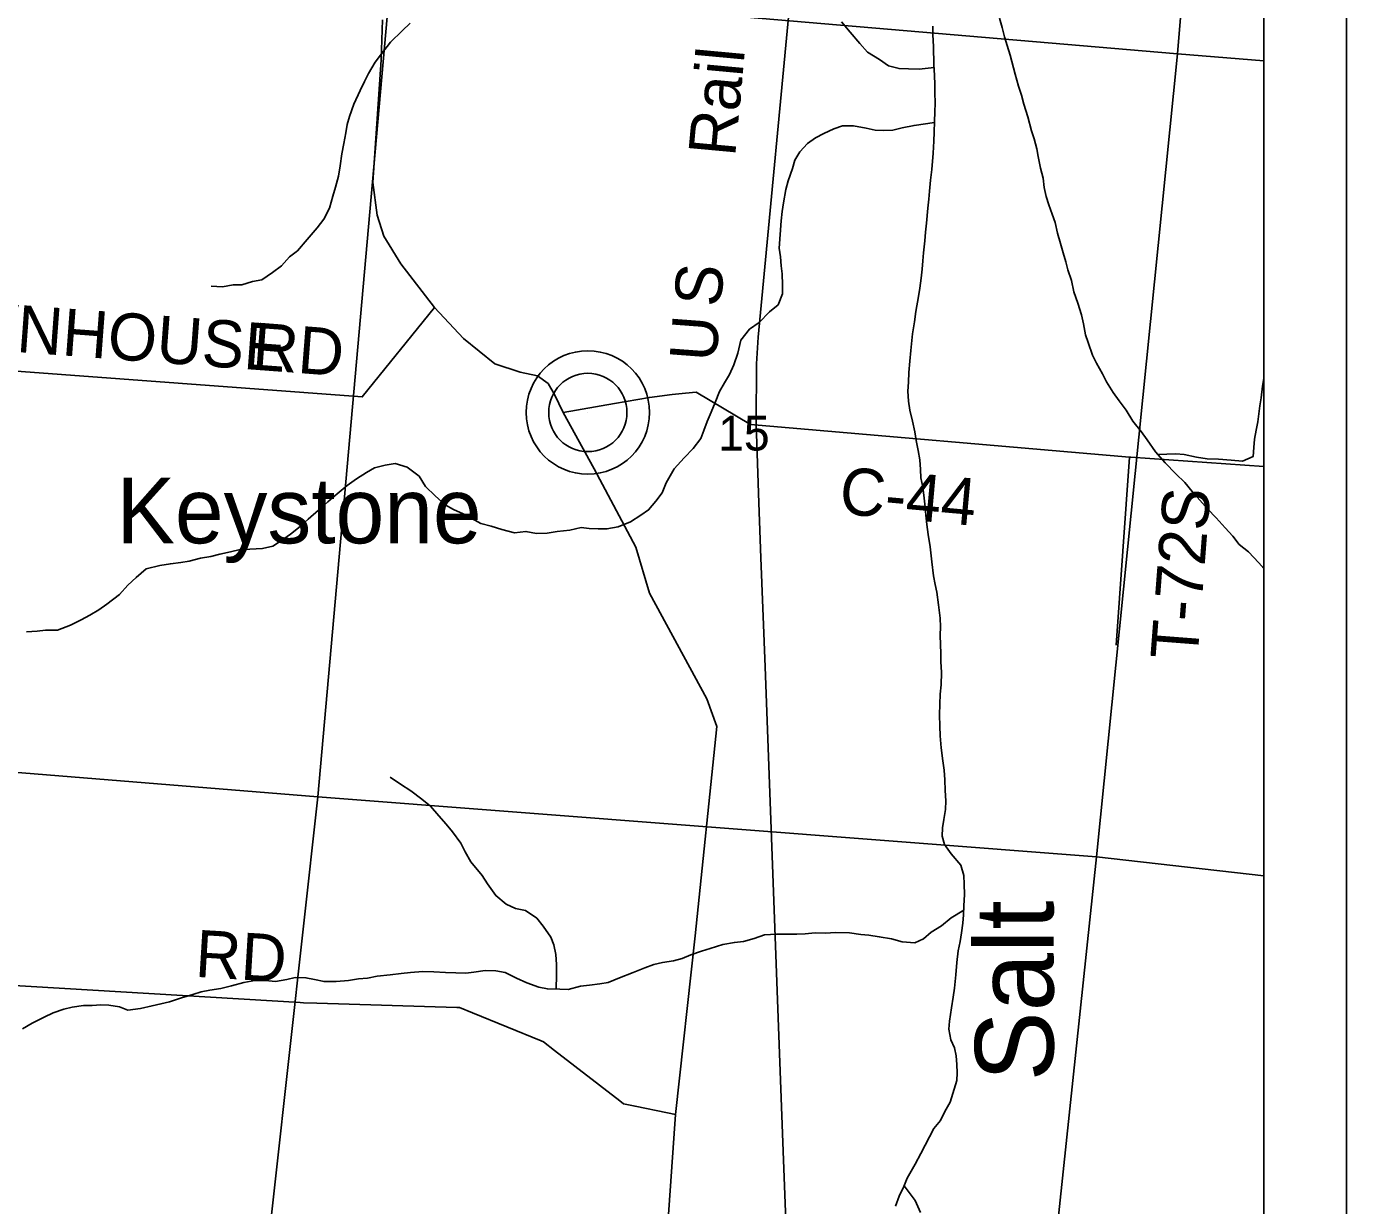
# Model space of a CAD drawing. Extents: x 0 to 34, y 0 to 22.
# Drawn here: x 28.825 to 30.417, y 16.193 to 17.615 of the extents above; entities that cross this region are included whole.
import ezdxf

# ---------------------------------------------------------------- set-up
doc = ezdxf.new("R2010")
doc.units = 0
for name, color, linetype in [('GM_X_Corporation', 7, 'Continuous'), ('GM_X_County_Road', 7, 'Continuous'), ('GM_X_County_Road_Text', 7, 'Continuous'), ('GM_X_Major_River', 7, 'Continuous'), ('GM_X_Major_River_Text', 7, 'Continuous'), ('GM_X_Minor_River', 7, 'Continuous'), ('GM_X_Rail_Line', 7, 'Continuous'), ('GM_X_Rail_Line_Text', 7, 'Continuous'), ('GM_X_Section_Text', 7, 'Continuous'), ('GM_X_Township_Road', 7, 'Continuous'), ('GM_X_Township_Road_Text', 7, 'Continuous'), ('GM_X_Unincorporated', 7, 'Continuous'), ('GM_X_Unincorporated_Location', 7, 'Continuous'), ('GM_X_Unincorporated_Text', 7, 'Continuous'), ('SH_Data', 7, 'Continuous')]:
    doc.layers.add(name, color=color, linetype=linetype)

msp = doc.modelspace()

# ---------------------------------------------------------------- linework, layer by layer
at = {"layer": 'GM_X_Corporation'}
msp.add_lwpolyline([(25.8273, 14.1), (30.3167, 14.1), (30.3167, 19.5906)], dxfattribs=at)
for points in [[(30.2969, 18.5954), (30.2127, 17.5822), (29.263, 17.6631), (29.2972, 18.6715)], [(30.3167, 17.5734), (30.3167, 18.5939), (30.2969, 18.5954), (30.2127, 17.5822)], [(28.2741, 17.7417), (29.263, 17.6631), (29.176, 16.6858), (28.199, 16.7653)], [(30.2127, 17.5822), (30.115, 16.6136), (29.176, 16.6858), (29.263, 17.6631)], [(30.3167, 16.5908), (30.3167, 17.5734), (30.2127, 17.5822), (30.115, 16.6136)], [(29.176, 16.6858), (29.0551, 15.5941), (28.1104, 15.671), (28.199, 16.7653)], [(30.115, 16.6136), (29.9973, 15.5007), (29.0551, 15.5941), (29.176, 16.6858)], [(30.3167, 15.4729), (30.3167, 16.5908), (30.115, 16.6136), (29.9973, 15.5007)]]:
    msp.add_lwpolyline(points, close=True, dxfattribs=at)
at = {"layer": 'GM_X_County_Road'}
for points in [[(29.5944, 16.119), (29.6075, 16.3028), (29.631, 16.5184), (29.6571, 16.7707), (29.6453, 16.804), (29.5759, 16.9315), (29.5594, 16.9871), (29.5094, 17.0817), (29.4719, 17.1493), (29.4613, 17.171), (29.4537, 17.1846), (29.4408, 17.1936), (29.42, 17.1981), (29.3897, 17.2082), (29.3517, 17.2387), (29.3169, 17.276), (29.2761, 17.3286), (29.2555, 17.3622), (29.2478, 17.3876), (29.2423, 17.427), (29.2523, 17.5746), (29.254, 17.6231)], [(29.4719, 17.1493), (29.534, 17.1603), (29.576, 17.1677), (29.6032, 17.1713), (29.6195, 17.1729), (29.6323, 17.1741), (29.6979, 17.1349), (30.1548, 17.0956), (30.1566, 17.0954), (30.3167, 17.0842)]]:
    msp.add_lwpolyline(points, dxfattribs=at)
at = {"layer": 'GM_X_Major_River'}
for points in [[(29.9176, 17.6152), (29.9179, 17.6054), (29.9186, 17.5906), (29.9191, 17.5693), (29.9198, 17.5557), (29.92, 17.5451), (29.9203, 17.5352), (29.9206, 17.5227), (29.9201, 17.5121), (29.9197, 17.5003), (29.9195, 17.4874), (29.9191, 17.4768), (29.9182, 17.4621), (29.9165, 17.4424), (29.9149, 17.4295), (29.9136, 17.4162), (29.9128, 17.4068), (29.9116, 17.3958), (29.9099, 17.3776), (29.9087, 17.367), (29.9082, 17.3564), (29.9065, 17.342), (29.9057, 17.3325), (29.9049, 17.3223), (29.9036, 17.3113), (29.902, 17.2996), (29.9004, 17.2893), (29.8972, 17.2712), (29.8956, 17.2587), (29.8932, 17.2443), (29.8911, 17.2242), (29.8899, 17.2113), (29.8886, 17.1977), (29.8882, 17.1859), (29.8877, 17.1753), (29.8883, 17.1632), (29.8901, 17.1522), (29.893, 17.1389), (29.896, 17.126), (29.8978, 17.1157), (29.8999, 17.1036), (29.9021, 17.0922), (29.9027, 17.0808), (29.9034, 17.0705), (29.9056, 17.0595), (29.9073, 17.0462), (29.9084, 17.0352), (29.9091, 17.0258), (29.9105, 17.0144), (29.9122, 17.0022), (29.9144, 16.9874), (29.9165, 16.9692), (29.9186, 16.9525), (29.9204, 16.9422), (29.9226, 16.9327), (29.9247, 16.9176), (29.9265, 16.9016), (29.9268, 16.891), (29.9267, 16.8811), (29.927, 16.8694), (29.9272, 16.8592), (29.9275, 16.8493), (29.9282, 16.836), (29.9277, 16.8212), (29.9264, 16.8099), (29.9263, 16.7977), (29.9258, 16.7849), (29.9261, 16.7712), (29.9264, 16.7594), (29.9277, 16.745), (29.9299, 16.7295), (29.9313, 16.7181), (29.9323, 16.7063)], [(29.9323, 16.7063), (29.9326, 16.6938), (29.9332, 16.6813), (29.9331, 16.6707), (29.9311, 16.6586), (29.9292, 16.6487), (29.9291, 16.6385), (29.9316, 16.6286), (29.9399, 16.6171), (29.9514, 16.6034), (29.9551, 16.5912), (29.9554, 16.5806), (29.9557, 16.5681), (29.9552, 16.5545), (29.9547, 16.5438), (29.9539, 16.5336), (29.9522, 16.5219), (29.9506, 16.5117), (29.9483, 16.5003), (29.9466, 16.4863), (29.9454, 16.4715), (29.9437, 16.4552), (29.9421, 16.4442), (29.9401, 16.4314), (29.9377, 16.4155), (29.9369, 16.4056), (29.9394, 16.3931), (29.9438, 16.3832), (29.946, 16.3737), (29.9467, 16.3631), (29.947, 16.3532), (29.9465, 16.3437), (29.9418, 16.3282), (29.9387, 16.3176), (29.9322, 16.3063), (29.9268, 16.2958), (29.9188, 16.286), (29.9138, 16.2758), (29.9034, 16.2558), (29.8965, 16.243), (29.8869, 16.226), (29.8827, 16.2162), (29.8773, 16.2045), (29.8726, 16.1924)]]:
    msp.add_lwpolyline(points, dxfattribs=at)
at = {"layer": 'GM_X_Minor_River'}
for points in [[(29.9982, 17.6251), (30.0015, 17.6137), (30.0041, 17.6027), (30.0075, 17.5921), (30.0108, 17.5803), (30.0168, 17.5576), (30.0212, 17.5431), (30.0246, 17.5321), (30.0276, 17.5215), (30.0324, 17.5059), (30.0365, 17.4892), (30.0399, 17.4794), (30.0432, 17.4676), (30.0447, 17.4581), (30.0476, 17.4441), (30.0506, 17.4319), (30.0521, 17.4209), (30.0543, 17.4099), (30.0577, 17.3997), (30.0618, 17.3887), (30.0651, 17.3784), (30.0681, 17.3659), (30.0718, 17.3534), (30.0748, 17.342), (30.0781, 17.331), (30.0807, 17.3215), (30.0848, 17.3086), (30.0878, 17.2949), (30.0927, 17.2812), (30.0971, 17.2672), (30.0994, 17.2562), (30.102, 17.2433), (30.1049, 17.2338), (30.1102, 17.2186), (30.115, 17.2091), (30.1222, 17.1962), (30.127, 17.1863), (30.1353, 17.1734), (30.1424, 17.1635), (30.1507, 17.1521), (30.159, 17.1392), (30.1691, 17.1266), (30.1762, 17.1167), (30.1864, 17.1019), (30.1977, 17.0886), (30.2108, 17.0756), (30.2214, 17.0649), (30.2304, 17.0543), (30.2398, 17.0436), (30.2488, 17.0334), (30.2594, 17.0223), (30.2703, 17.0105), (30.2793, 17.0002), (30.2872, 16.9903), (30.2985, 16.9816), (30.3109, 16.9683), (30.3167, 16.9613)], [(29.2876, 17.6189), (29.2777, 17.6098), (29.2637, 17.5959), (29.253, 17.5819), (29.2454, 17.5721), (29.2371, 17.5584), (29.2325, 17.5486), (29.2271, 17.5376), (29.2195, 17.5214), (29.2142, 17.5066), (29.2115, 17.4968), (29.2099, 17.4869), (29.2076, 17.474), (29.2049, 17.4615), (29.2029, 17.4468), (29.201, 17.4346), (29.1972, 17.4214), (29.1941, 17.4104), (29.1902, 17.396), (29.1834, 17.3828), (29.1754, 17.3722), (29.1632, 17.3582), (29.1515, 17.3446), (29.142, 17.3371), (29.1321, 17.3262), (29.1215, 17.3182), (29.1086, 17.3096), (29.0973, 17.3074), (29.0844, 17.3036), (29.0738, 17.3033), (29.061, 17.3011), (29.0473, 17.3019)], [(29.9193, 17.5655), (29.9011, 17.5634), (29.8883, 17.5638), (29.877, 17.5643), (29.8641, 17.5677), (29.8532, 17.575), (29.8389, 17.5841), (29.8295, 17.5944), (29.8182, 17.6081), (29.8077, 17.6207)], [(29.9196, 17.4992), (29.8952, 17.4956), (29.8808, 17.4926), (29.8694, 17.49), (29.8581, 17.4897), (29.8483, 17.4901), (29.8373, 17.4924), (29.8222, 17.4951), (29.8086, 17.4952), (29.7984, 17.4914), (29.7863, 17.4858), (29.7764, 17.4809), (29.7666, 17.4738), (29.7575, 17.464), (29.7514, 17.4538), (29.7483, 17.4439), (29.7433, 17.4288), (29.7406, 17.4182), (29.7375, 17.4023), (29.736, 17.3917), (29.7348, 17.3807), (29.7324, 17.3477), (29.7339, 17.3371), (29.7349, 17.3265), (29.736, 17.3166), (29.7364, 17.3033), (29.7363, 17.2927), (29.7313, 17.2795), (29.7207, 17.2708), (29.7082, 17.258), (29.6968, 17.2501), (29.6862, 17.2368), (29.6827, 17.2209), (29.6777, 17.2069), (29.6724, 17.1952), (29.6663, 17.1854), (29.6606, 17.1748), (29.6552, 17.1615), (29.6503, 17.1498), (29.6457, 17.1385), (29.6415, 17.1279), (29.638, 17.118), (29.6285, 17.1059), (29.6179, 17.0946), (29.6058, 17.0814), (29.5962, 17.0648), (29.5913, 17.0526), (29.5837, 17.0424), (29.5749, 17.0319), (29.5655, 17.0255), (29.5533, 17.0176), (29.5382, 17.0116), (29.5246, 17.009), (29.514, 17.009), (29.5034, 17.0095), (29.4936, 17.0106), (29.48, 17.0077), (29.4645, 17.0058), (29.4527, 17.004), (29.4399, 17.0037), (29.427, 17.006), (29.4131, 17.0042), (29.398, 17.0084), (29.3851, 17.0123), (29.3727, 17.0157), (29.3617, 17.0218), (29.3512, 17.0272), (29.3395, 17.0326), (29.3297, 17.0383), (29.3176, 17.049), (29.306, 17.0604), (29.2981, 17.0726), (29.2838, 17.0836), (29.2694, 17.0878), (29.2573, 17.086), (29.2444, 17.0827), (29.2346, 17.077), (29.2228, 17.0695), (29.2115, 17.0616), (29.1993, 17.0514), (29.1883, 17.0416), (29.177, 17.0318), (29.1644, 17.0208), (29.1546, 17.0118), (29.1432, 17.0028), (29.1322, 16.9952), (29.122, 16.9881), (29.1095, 16.9855), (29.094, 16.9848), (29.0826, 16.9844), (29.0709, 16.9815), (29.058, 16.9785), (29.0471, 16.9759), (29.0346, 16.9737), (29.021, 16.9703), (29.0108, 16.9685), (28.9983, 16.967), (28.9854, 16.9648), (28.9691, 16.9611), (28.957, 16.9505), (28.9471, 16.9411)], [(30.1891, 17.0987), (30.2106, 17.0995), (30.2208, 17.0987), (30.2355, 17.0956), (30.2487, 17.0936), (30.2623, 17.0932), (30.2774, 17.092), (30.291, 17.0908), (30.3039, 17.0964), (30.3047, 17.1074), (30.3055, 17.1173), (30.3078, 17.1282), (30.3097, 17.1381), (30.3109, 17.1479), (30.3121, 17.1574), (30.3137, 17.1673), (30.3152, 17.1813), (30.3167, 17.1903)], [(28.9471, 16.9411), (28.9369, 16.9298), (28.9217, 16.9185), (28.9119, 16.9113), (28.9013, 16.9049), (28.8906, 16.8993), (28.8778, 16.8929), (28.8622, 16.8869), (28.8475, 16.887), (28.8377, 16.8859), (28.8248, 16.8848)], [(29.4635, 16.454), (29.4637, 16.4713), (29.4637, 16.4838), (29.463, 16.496), (29.4608, 16.5074), (29.4571, 16.5169), (29.448, 16.5302), (29.4401, 16.5397), (29.4266, 16.5488), (29.4145, 16.5515), (29.4032, 16.5565), (29.3907, 16.5668), (29.3806, 16.5809), (29.3742, 16.5912), (29.3607, 16.6075), (29.3536, 16.6197), (29.3487, 16.6299), (29.3385, 16.6436), (29.331, 16.6531), (29.322, 16.663), (29.3118, 16.6748), (29.3017, 16.6832), (29.2881, 16.6931), (29.2757, 16.7012), (29.2632, 16.7096)], [(29.9549, 16.5493), (29.9398, 16.5401), (29.928, 16.5303), (29.9159, 16.5227), (29.9064, 16.5148), (29.8962, 16.5099), (29.8807, 16.5111), (29.8679, 16.5146), (29.8531, 16.5173), (29.8407, 16.5193), (29.8309, 16.5201), (29.8173, 16.522), (29.8003, 16.5225), (29.7882, 16.5214), (29.7757, 16.5218), (29.7636, 16.5208), (29.7538, 16.5204), (29.7292, 16.5205), (29.7148, 16.5195), (29.7023, 16.515), (29.6895, 16.5116), (29.6785, 16.5105), (29.6645, 16.5079), (29.649, 16.5031), (29.6388, 16.4997), (29.6259, 16.4956), (29.6153, 16.4911), (29.6051, 16.4881), (29.5918, 16.4863), (29.5813, 16.4837), (29.5703, 16.4799), (29.5563, 16.4743), (29.54, 16.4676), (29.526, 16.4619), (29.5161, 16.4605), (29.5037, 16.459), (29.4927, 16.4576), (29.4779, 16.4538), (29.4681, 16.4539), (29.453, 16.4543), (29.4424, 16.4563), (29.4281, 16.4616), (29.4156, 16.4674), (29.4021, 16.4743), (29.3907, 16.4762), (29.3779, 16.4766), (29.3643, 16.4744), (29.3544, 16.4733), (29.3427, 16.4738), (29.3299, 16.4742), (29.3159, 16.475), (29.3027, 16.4755), (29.2879, 16.474), (29.2766, 16.4729), (29.2633, 16.4715), (29.2478, 16.4697), (29.2361, 16.4674), (29.2251, 16.4663), (29.213, 16.4645), (29.1983, 16.4634), (29.1836, 16.4631), (29.1719, 16.4658), (29.1617, 16.4678), (29.1488, 16.4682), (29.1386, 16.4656), (29.125, 16.4634), (29.1129, 16.4646), (29.1, 16.4643), (29.0868, 16.4621), (29.072, 16.4579), (29.0592, 16.455), (29.0459, 16.4528), (29.0354, 16.4509), (29.0255, 16.4475), (29.0115, 16.4434), (28.9971, 16.4386), (28.9869, 16.4363), (28.9763, 16.4341), (28.9623, 16.4308), (28.9468, 16.4286), (28.937, 16.4328), (28.9242, 16.4347), (28.9143, 16.4352), (28.9038, 16.4345), (28.8935, 16.4345), (28.8799, 16.4323), (28.8697, 16.4301), (28.8568, 16.4256), (28.8462, 16.4203), (28.8315, 16.4132), (28.8201, 16.406)], [(29.883, 16.217), (29.8964, 16.1991), (29.9027, 16.1846)]]:
    msp.add_lwpolyline(points, dxfattribs=at)
at = {"layer": 'GM_X_Rail_Line'}
msp.add_lwpolyline([(29.7476, 15.9863), (29.7374, 16.2588), (29.7316, 16.4086), (29.7154, 16.8428), (29.7103, 16.9741), (29.708, 17.0405), (29.7045, 17.1358), (29.7049, 17.2083), (29.7071, 17.2403), (29.7493, 17.6862)], dxfattribs=at)
at = {"layer": 'GM_X_Township_Road'}
msp.add_line((30.1548, 17.0956), (30.1387, 16.8689), dxfattribs=at)
for points in [[(27.9899, 17.2605), (29.2296, 17.1682), (29.3169, 17.276)], [(28.688, 16.4656), (29.1549, 16.438), (29.1587, 16.4377), (29.1748, 16.4372), (29.3439, 16.4321), (29.3469, 16.432), (29.3625, 16.4256), (29.4454, 16.3917), (29.4482, 16.3906), (29.4615, 16.3802), (29.5401, 16.3192), (29.5445, 16.3158), (29.5586, 16.3129), (29.5976, 16.3049), (29.6075, 16.3028)]]:
    msp.add_lwpolyline(points, dxfattribs=at)
at = {"layer": 'GM_X_Unincorporated'}
for radius in [0.0744, 0.0472]:
    msp.add_circle((29.5017, 17.1495), radius, dxfattribs=at)
at = {"layer": 'GM_X_Unincorporated_Location'}
msp.add_line((29.5017, 17.1495), (29.5017, 17.1495), dxfattribs=at)
at = {"layer": 'SH_Data'}
for points in [[(23.4167, 21), (30.4167, 21), (30.4167, 14), (23.4167, 14)], [(23.5167, 20.9), (30.3167, 20.9), (30.3167, 14.1), (23.5167, 14.1)]]:
    msp.add_lwpolyline(points, close=True, dxfattribs=at)

# ---------------------------------------------------------------- texts
at = {"layer": 'GM_X_County_Road_Text'}
msp.add_text('C-44', height=0.05682, rotation=354.8369, dxfattribs=at).set_placement((29.8036, 17.0276))
at = {"layer": 'GM_X_Major_River_Text'}
msp.add_text('Salt', height=0.09471, rotation=90.0001, dxfattribs=at).set_placement((30.0633, 16.3428))
at = {"layer": 'GM_X_Rail_Line_Text'}
for s, height, rotation, p in [('Rail', 0.05663, 84.7218, (29.6792, 17.457)), ('S', 0.0566, 84.4602, (29.6615, 17.2756)), ('U', 0.0566, 85.7149, (29.6566, 17.2096))]:
    msp.add_text(s, height=height, rotation=rotation, dxfattribs=at).set_placement(p)
at = {"layer": 'GM_X_Section_Text'}
msp.add_text('15', height=0.04186, rotation=0, dxfattribs=at).set_placement((29.6587, 17.1036))
at = {"layer": 'GM_X_Township_Road_Text'}
for s, rotation, p in [('TOWNHOUSE', 355.732, (28.635, 17.2357)), ('RD', 355.5623, (29.0959, 17.2015)), ('T-72S', 85.6016, (30.2367, 16.85)), ('RD', 356.5467, (29.0272, 16.469))]:
    msp.add_text(s, height=0.05682, rotation=rotation, dxfattribs=at).set_placement(p)
at = {"layer": 'GM_X_Unincorporated_Text'}
msp.add_text('Keystone', height=0.07898, rotation=0, dxfattribs=at).set_placement((28.9333, 16.9917))

doc.saveas('drawing.dxf')
